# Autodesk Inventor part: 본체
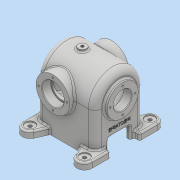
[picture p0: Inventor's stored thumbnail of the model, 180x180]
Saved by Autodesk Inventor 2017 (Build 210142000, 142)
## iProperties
Part Number: 본체
Material: 일반
Document SubType Name: Modeling
Designer: MRC
Density: 1 g/cm^3
Appearance: 기본값
Author: MRC
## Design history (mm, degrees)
sketch "스케치1"
  geometry: L1 (0, 45)-(0, 45); L2 (45, 0)-(45, -76); L3 (45, -76)-(-45, -76); L4 (-45, -76)-(-45, 0); L5 (-20, -53)-(20, -53); L6 (20, -53)-(20, -76); L7 (20, -76)-(-20, -76); L8 (-20, -76)-(-20, -53); A1 r 45 centre (0, 0) between (0, 45) and (-45, 0); A2 r 45 centre (0, 0) between (45, 0) and (0, 45); 2 further points
  constraints: 16 end point, 4 parallel, 4 point on circle, 4 tangent, 2 centre point, 2 horizontal, 2 horizontal alignment, 2 perpendicular, 2 point on line, 1 concentric
  dimensions: "d0" = 90 distance of L2.end L3.end; "d1" = 121 distance of point (45, 45) L2.end; "d2" = 45 radius of A1; "d3" = 45 distance from line of point (0, 0) L2; "d4" = 40 distance of L5.start L5.end; "d5" = 23 distance of L5.end L6.end; "d6" = 20 distance from line of L8 point (0, 0)
extrude "돌출1" new body sketch "스케치1" stored distance "d7" = 108; taper "d8" = 0 deg
sketch "스케치4"
  geometry: L1 (-54, -76)-(-54, 0) reference; L2 (54, 0)-(54, -76) reference; C1 r 31 at (14, 0); 1 further point
  constraints: 1 centre point, 1 horizontal alignment
  dimensions: "d12" = 62 diameter of C1; "d14" = 40 distance from line of C1.centre L2
extrude "돌출3" join sketch "스케치4" stored distance "d15" = 108; taper "d16" = 0 deg
sketch "스케치5"
  geometry: C1 r 28.5 at (0, 0); 1 further point
  constraints: 1 centre point, 1 coincident
  dimensions: "d17" = 57 diameter of C1
extrude "돌출4" join sketch "스케치5" distance "d18" = 6; taper "d19" = 0 deg
node "작업 평면1"
sketch "스케치6"
  geometry: L1 (60, -28.5)-(60, 28.5) reference; C1 r 7.5 at (-14, 0); 1 further point
  constraints: 1 centre point, 1 horizontal alignment
  dimensions: "d21" = 15 diameter of C1; "d22" = 74 distance from line of C1.centre L1
extrude "돌출5" join sketch "스케치6" stored distance "d23" = 6; taper "d24" = 0 deg
sketch "스케치7"
  geometry: L1 (45, 33)-(45, 0); L2 (45, 0)-(-60, 0); L3 (-60, 0)-(-60, 16.5); L4 (-60, 16.5)-(-45, 16.5); L5 (-45, 16.5)-(-45, 33); L6 (-42, 36)-(42, 36); L7 (-60, 28.5)-(-60, -28.5) reference; A1 r 3 centre (-42, 33) between (-42, 36) and (-45, 33); A2 r 3 centre (42, 33) between (45, 33) and (42, 36); 3 further points
  constraints: 12 end point, 4 horizontal alignment, 4 perpendicular, 4 point on circle, 4 point on line, 4 tangent, 2 centre point, 1 equal radius, 1 horizontal, 1 vertical
  dimensions: "d25" = 16.5 distance of L2.end L3.end; "d26" = 105 distance of L1.end L2.end; "d27" = 36 distance of point (45, 36) L1.end; "d28" = 90 distance of point (-45, 36) point (45, 36); "d29" = 0 distance between parallel lines of L3 L7; "d30" = 3 radius of A1
revolve "회전1" sketch "스케치7" stored, may be unused: angle "d31" = 90 deg
sketch "스케치9"
  geometry: L1 (-36, -76)-(36, -76); L2 (36, -76)-(36, -27); L3 (-36, -27)-(-36, -76); L4 (45, -76)-(20, -76) reference; L5 (45, 0)-(45, -76) reference; L6 (-45, -76)-(-45, 0) reference; A1 r 45 centre (0, 0) between (-36, -27) and (45, 0); 1 further point
  constraints: 6 end point, 3 point on circle, 1 centre point, 1 coincident, 1 horizontal, 1 parallel, 1 perpendicular, 1 point on line
  dimensions: "d38" = 90 diameter of A1; "d39" = 0 distance between parallel lines of L4 L1; "d40" = 9 distance between parallel lines of L5 L2; "d41" = 9 distance between parallel lines of L3 L6
extrude "돌출6" cut sketch "스케치9" stored distance "d42" = 90; taper "d43" = 0 deg
hole "구멍1" diameter "d46" = 5.188; stored, may be unused: countersink angle "d50" = 90 deg, drill point angle "d52" = 118 deg; dims "d44" = 10, "d45" = 10, "d47" = 12, "d48" = 4, "d49" = 2, "d51" = 100
hole "구멍2" diameter "d62" = 35; stored, may be unused: countersink angle "d66" = 90 deg, drill point angle "d68" = 118 deg; dims "d60" = 10, "d61" = 10, "d63" = 12, "d64" = 40, "d65" = 16, "d67" = 50
hole "구멍3" diameter "d71" = 35; stored, may be unused: countersink angle "d75" = 90 deg, drill point angle "d77" = 118 deg; dims "d69" = 10, "d70" = 10, "d72" = 12, "d73" = 40, "d74" = 16, "d76" = 50
sketch "스케치11"
  geometry: L1 (0, 0)-(-23, 0)
  constraints: 2 end point, 1 horizontal
  dimensions: "d78" = 23 distance of L1.start L1.end
hole "구멍4" sketch "스케치11" at (-23, 0) diameter "d79" = 3.242; stored, may be unused: countersink angle "d83" = 90 deg, drill point angle "d85" = 118 deg; dims "d80" = 8, "d81" = 40, "d82" = 16, "d84" = 10
sketch "스케치12"
  geometry: L1 (0, 0)-(-26, 0); C1 r 17.5 at (0, 0) reference; 1 further point
  constraints: 2 end point, 1 horizontal
  dimensions: "d89" = 26 distance of L1.start L1.end
hole "구멍5" sketch "스케치12" at (-26, 0) diameter "d90" = 3.242; stored, may be unused: countersink angle "d94" = 90 deg, drill point angle "d96" = 118 deg; dims "d91" = 8, "d92" = 40, "d93" = 16, "d95" = 10
sketch "스케치13"
  geometry: L1 (53, -20)-(53, 20) reference; L2 (76, 20)-(76, 45) reference; 2 further points
  constraints: 1 horizontal alignment, 1 other
  dimensions: "d101" = 35 distance from line of point (41, 0) L2
feature "엠보싱1" sketch "스케치13" dims "d0" = 90, "d1" = 121, "d2" = 45, "d3" = 45, "d4" = 40, "d5" = 23, "d6" = 20, "d12" = 62, "d14" = 40, "d102" = 0.5, "d103" = 0
sketch "스케치16"
  geometry: L1 (99, 25)-(99, 9) reference; L2 (99, 9)-(9, 9) reference; L3 (9, 9)-(9, 25) reference; L4 (9, 25)-(0, 25) reference; L5 (0, 0)-(0, 25) reference; L6 (108, 0)-(0, 0) reference; L7 (108, 25)-(108, 0) reference; L8 (108, 25)-(99, 25) reference; L9 (99, 81)-(99, 65) reference; L10 (99, 65)-(108, 65) reference; L11 (108, 90)-(108, 65) reference; L12 (0, 90)-(108, 90) reference; L13 (0, 65)-(0, 90) reference; L14 (0, 65)-(9, 65) reference; L15 (9, 65)-(9, 81) reference; L16 (9, 81)-(99, 81) reference; L17 (91.21, -20.693)-(82, 0); L18 (108, 0)-(0, 0) reference; L19 (108, 18)-(118, 18); L20 (118, 18)-(118, -15); L21 (54, 45)-(33.69, 45); L22 (54, 45)-(54, 29.29); L23 (108, 72)-(118, 72); L24 (118, 72)-(118, 105); L25 (91.21, 110.693)-(82, 90); L26 (16.79, -20.693)-(26, 0); L27 (-10, 18)-(-10, -15); L28 (0, 18)-(-10, 18); L29 (-10, 72)-(-10, 105); L30 (0, 72)-(-10, 72); L31 (16.79, 110.693)-(26, 90); L32 (108, 72)-(108, 90); L33 (108, 90)-(82, 90); L34 (26, 90)-(0, 90); L35 (0, 90)-(0, 72); L36 (0, 18)-(0, 0); L37 (26, 0)-(0, 0); L38 (82, 0)-(108, 0); L39 (108, 18)-(108, 0); A1 r 14 centre (104, -15) between (91.21, -20.693) and (118, -15); A2 r 14 centre (104, 105) between (118, 105) and (91.21, 110.693); A3 r 14 centre (4, -15) between (-10, -15) and (16.79, -20.693); A4 r 14 centre (4, 105) between (16.79, 110.693) and (-10, 105)
  constraints: 44 end point, 18 symmetric about line, 8 point on circle, 7 collinear, 4 centre point, 4 point on line, 2 horizontal, 2 perpendicular, 2 tangent, 1 horizontal alignment, 1 vertical, 3 other
  dimensions: "d111" = 18 distance between parallel lines of L6 L19; "d112" = 28 diameter of A1; "d113" = 60 vertical distance of L20.end L21.start; "d114" = 36 distance from line of L17.end L20; "d115" = 64 distance from line of L20 L21.start; "d116" = 4.29025 distance from line of L22.end L8; "d117" = 74.30956 distance from line of L21.end L7
extrude "돌출7" join sketch "스케치16" distance "d118" = 12; taper "d119" = 0 deg
hole "구멍6" diameter "d122" = 6.6; stored, may be unused: countersink angle "d126" = 90 deg, drill point angle "d128" = 118 deg; dims "d120" = 10, "d121" = 10, "d123" = 8, "d124" = 18, "d125" = 2, "d127" = 10
hole "구멍7" diameter "d131" = 6.6; stored, may be unused: countersink angle "d135" = 90 deg, drill point angle "d137" = 118 deg; dims "d129" = 10, "d130" = 10, "d132" = 8, "d133" = 18, "d134" = 2, "d136" = 10
hole "구멍8" diameter "d140" = 6.6; stored, may be unused: countersink angle "d144" = 90 deg, drill point angle "d146" = 118 deg; dims "d138" = 10, "d139" = 10, "d141" = 8, "d142" = 18, "d143" = 2, "d145" = 10
hole "구멍9" diameter "d149" = 6.6; stored, may be unused: countersink angle "d153" = 90 deg, drill point angle "d155" = 118 deg; dims "d147" = 10, "d148" = 10, "d150" = 8, "d151" = 18, "d152" = 2, "d154" = 10
chamfer "모따기1" distance "d156" = 1; stored, may be unused: second distance "d157" = 2, angle "d158" = 45 deg
fillet "모깎기1" dims "d159" = 0.3
fillet "모깎기2" dims "d160" = 3
fillet "모깎기9" dims "d167" = 12
fillet "모깎기10" dims "d168" = 3
fillet "모깎기11" dims "d169" = 3
node "솔리드1"
mirror "미러1"
pattern_circular "원형 패턴1" dims angle "d87" = 360 deg
pattern_circular "원형 패턴2" dims angle "d98" = 360 deg
mirror "미러2"
node "투영된 루프3"
node "투영된 루프4"
other parameters: "d20" = 49
